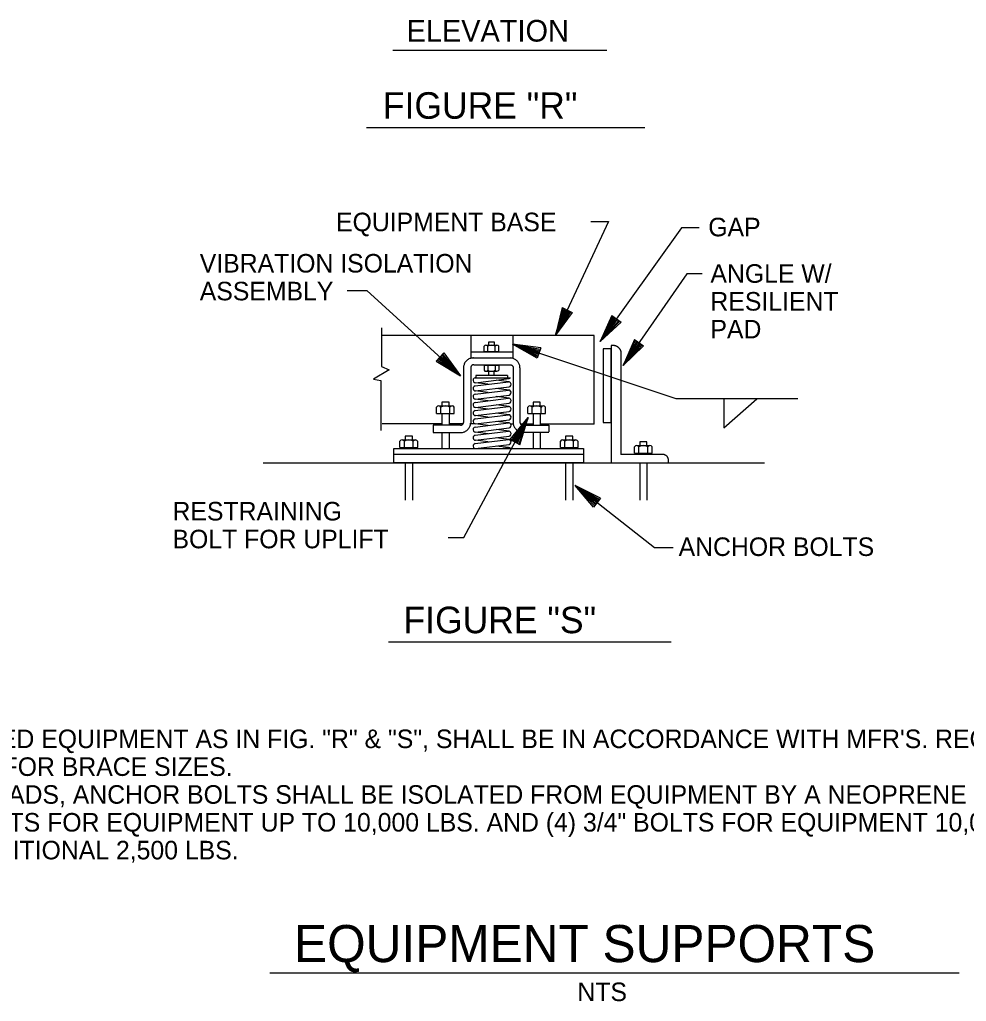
# Model space of a CAD drawing. Extents: x 10040.55 to 10045.84, y 10033.26 to 10035.76.
# Drawn here: x 10042.746 to 10043.256, y 10034.644 to 10035.174 of the extents above; entities that cross this region are included whole.
import ezdxf

# ---------------------------------------------------------------- set-up
doc = ezdxf.new("R2010")
doc.units = 0
doc.layers.add('Level 2', color=7, linetype='Continuous')

msp = doc.modelspace()

# ---------------------------------------------------------------- linework, layer by layer
at = {"layer": 'Level 2'}
for p, q in [((10042.94689, 10035.15714), (10043.06232, 10035.15714)), ((10042.93277, 10035.11534), (10043.08279, 10035.11534)), ((10043.03826, 10035.01825), (10043.03459, 10035.00334)), ((10043.03826, 10035.01825), (10043.04371, 10035.01569)), ((10043.03459, 10035.00334), (10043.03895, 10035.01793)), ((10043.03459, 10035.00334), (10043.03972, 10035.01759)), ((10043.03459, 10035.00334), (10043.04032, 10035.01728)), ((10043.04096, 10035.017), (10043.03459, 10035.00334)), ((10043.03459, 10035.00334), (10043.04164, 10035.01667)), ((10043.03459, 10035.00334), (10043.04232, 10035.01636)), ((10043.03459, 10035.00334), (10043.04297, 10035.01604)), ((10043.04371, 10035.01569), (10043.03459, 10035.00334)), ((10043.06508, 10035.01396), (10043.05876, 10034.99997)), ((10043.05876, 10034.99997), (10043.06571, 10035.01351)), ((10043.05876, 10034.99997), (10043.06641, 10035.01304)), ((10043.06508, 10035.01396), (10043.06998, 10035.01045)), ((10043.05876, 10034.99997), (10043.06694, 10035.01264)), ((10043.06751, 10035.01223), (10043.05876, 10034.99997)), ((10043.05876, 10034.99997), (10043.06811, 10035.01178)), ((10043.05876, 10034.99997), (10043.06873, 10035.01136)), ((10043.05876, 10034.99997), (10043.06931, 10035.01093)), ((10043.06998, 10035.01045), (10043.05876, 10034.99997)), ((10043.05557, 10035.00319), (10042.94107, 10035.00319)), ((10043.05557, 10034.95544), (10043.05557, 10035.00319)), ((10042.99614, 10034.99466), (10042.99614, 10034.99741)), ((10042.99713, 10034.998), (10043.00304, 10034.998)), ((10042.99809, 10034.99466), (10042.99809, 10034.99741)), ((10043.00206, 10034.99466), (10043.00206, 10034.99741)), ((10043.00403, 10034.99466), (10043.00403, 10034.99739)), ((10043.01153, 10034.99855), (10043.09949, 10034.96918)), ((10043.02583, 10034.9938), (10043.01153, 10034.99855)), ((10043.02484, 10034.99092), (10043.01153, 10034.99855)), ((10043.02676, 10034.99664), (10043.01153, 10034.99855)), ((10043.01153, 10034.99855), (10043.02535, 10034.99238)), ((10043.01153, 10034.99855), (10043.02627, 10034.99509)), ((10043.01153, 10034.99855), (10043.02511, 10034.9917)), ((10043.01153, 10034.99855), (10043.02558, 10034.99308)), ((10043.01153, 10034.99855), (10043.02604, 10034.99447)), ((10043.01153, 10034.99855), (10043.02652, 10034.99591)), ((10043.06473, 10034.99783), (10043.06473, 10034.93447)), ((10043.06656, 10034.99783), (10043.06473, 10034.99783)), ((10043.07724, 10035.00113), (10043.07113, 10034.98704)), ((10043.07113, 10034.98704), (10043.07786, 10035.00069)), ((10043.07113, 10034.98704), (10043.07857, 10035.00023)), ((10043.07113, 10034.98704), (10043.0791, 10034.99982)), ((10043.07969, 10034.99944), (10043.07113, 10034.98704)), ((10043.07113, 10034.98704), (10043.0803, 10034.999)), ((10043.07113, 10034.98704), (10043.08093, 10034.99858)), ((10043.07113, 10034.98704), (10043.08151, 10034.99816)), ((10043.08218, 10034.99768), (10043.07113, 10034.98704)), ((10043.07724, 10035.00113), (10043.08218, 10034.99768)), ((10042.97029, 10034.98933), (10042.97436, 10034.99378)), ((10042.98345, 10034.98142), (10042.97281, 10034.99209)), ((10042.98345, 10034.98142), (10042.97331, 10034.99266)), ((10042.98345, 10034.98142), (10042.9738, 10034.99319)), ((10042.97436, 10034.99378), (10042.98345, 10034.98142)), ((10042.98891, 10034.99439), (10043.0118, 10034.99439)), ((10042.99614, 10034.99466), (10043.00403, 10034.99466)), ((10043.02676, 10034.99664), (10043.02484, 10034.99092)), ((10043.06035, 10034.99595), (10043.06035, 10034.95638)), ((10043.06473, 10034.99595), (10043.06035, 10034.99595)), ((10043.06473, 10034.95638), (10043.06473, 10034.99595)), ((10043.0699, 10034.99424), (10043.0699, 10034.93901)), ((10042.97029, 10034.98933), (10042.98345, 10034.98142)), ((10042.98345, 10034.98142), (10042.97081, 10034.98991)), ((10042.98345, 10034.98142), (10042.97136, 10034.99054)), ((10042.98345, 10034.98142), (10042.97183, 10034.99102)), ((10042.97229, 10034.99155), (10042.98345, 10034.98142)), ((10042.99055, 10034.98744), (10043.01017, 10034.98744)), ((10042.99614, 10034.98724), (10043.00403, 10034.98724)), ((10042.99614, 10034.98724), (10042.99614, 10034.98449)), ((10042.99809, 10034.98724), (10042.99809, 10034.98449)), ((10043.00206, 10034.98724), (10043.00206, 10034.98449)), ((10043.00403, 10034.98724), (10043.00403, 10034.98451)), ((10042.98503, 10034.98577), (10042.98503, 10034.95627)), ((10042.98889, 10034.98586), (10042.98889, 10034.95599)), ((10043.00869, 10034.98171), (10042.99166, 10034.98171)), ((10042.99166, 10034.98171), (10042.99166, 10034.98046)), ((10042.99713, 10034.9839), (10043.00304, 10034.9839)), ((10042.99853, 10034.98393), (10042.99853, 10034.98169)), ((10043.00157, 10034.98169), (10043.00157, 10034.98393)), ((10043.00869, 10034.98171), (10043.00869, 10034.98046)), ((10043.01178, 10034.98577), (10043.01178, 10034.95629)), ((10043.01548, 10034.98577), (10043.01548, 10034.95629)), ((10042.99128, 10034.98046), (10043.0104, 10034.98046)), ((10042.9983, 10034.97689), (10042.99128, 10034.97774)), ((10042.99129, 10034.97602), (10043.00932, 10034.97824)), ((10042.99155, 10034.97775), (10043.00957, 10034.97997)), ((10043.00958, 10034.97824), (10043.00255, 10034.9791)), ((10042.99128, 10034.97158), (10043.0093, 10034.9738)), ((10042.99831, 10034.97245), (10042.9913, 10034.9733)), ((10042.99155, 10034.96888), (10043.00957, 10034.97109)), ((10042.99156, 10034.97331), (10043.00959, 10034.97553)), ((10043.0096, 10034.9738), (10043.00256, 10034.97467)), ((10042.97169, 10034.96528), (10042.97885, 10034.96528)), ((10042.9983, 10034.96801), (10042.99128, 10034.96886)), ((10042.99129, 10034.96715), (10043.00932, 10034.96936)), ((10042.99156, 10034.96444), (10043.00959, 10034.96666)), ((10043.00958, 10034.96936), (10043.00255, 10034.97023)), ((10043.0096, 10034.96493), (10043.00256, 10034.96579)), ((10043.02089, 10034.96528), (10043.02805, 10034.96528)), ((10043.09949, 10034.96918), (10043.16543, 10034.96918)), ((10043.12538, 10034.96915), (10043.12538, 10034.9534)), ((10043.12538, 10034.9534), (10043.14317, 10034.96902)), ((10042.97049, 10034.96122), (10042.97049, 10034.96455)), ((10042.97049, 10034.96122), (10042.98004, 10034.96122)), ((10042.97285, 10034.96122), (10042.97285, 10034.96455)), ((10042.97331, 10034.96122), (10042.97331, 10034.95489)), ((10042.97724, 10034.96122), (10042.97724, 10034.95496)), ((10042.97766, 10034.96122), (10042.97766, 10034.96455)), ((10042.98004, 10034.96122), (10042.98004, 10034.96453)), ((10042.99128, 10034.96271), (10043.0093, 10034.96493)), ((10042.9983, 10034.95914), (10042.99128, 10034.95999)), ((10042.99129, 10034.95827), (10043.00932, 10034.96049)), ((10042.99831, 10034.96357), (10042.9913, 10034.96443)), ((10042.99155, 10034.96), (10043.00957, 10034.96222)), ((10043.00958, 10034.96049), (10043.00255, 10034.96135)), ((10043.01969, 10034.96122), (10043.01969, 10034.96455)), ((10043.01969, 10034.96122), (10043.02924, 10034.96122)), ((10043.02205, 10034.96122), (10043.02205, 10034.96455)), ((10043.02251, 10034.96122), (10043.02251, 10034.95489)), ((10043.02644, 10034.96122), (10043.02644, 10034.95484)), ((10043.02685, 10034.96122), (10043.02685, 10034.96455)), ((10043.02924, 10034.96122), (10043.02924, 10034.96453)), ((10042.97331, 10034.95552), (10042.94107, 10034.95555)), ((10042.98342, 10034.95492), (10042.96871, 10034.95492)), ((10042.96871, 10034.95492), (10042.96871, 10034.95088)), ((10042.98479, 10034.9555), (10042.97724, 10034.95551)), ((10042.99138, 10034.9555), (10042.98878, 10034.9555)), ((10042.99128, 10034.95383), (10043.0093, 10034.95605)), ((10042.99831, 10034.9547), (10042.9913, 10034.95555)), ((10042.99156, 10034.95556), (10043.00959, 10034.95778)), ((10043.0096, 10034.95605), (10043.00256, 10034.95692)), ((10043.01018, 10034.94713), (10043.01998, 10034.95894)), ((10043.01185, 10034.95548), (10043.01044, 10034.95548)), ((10043.01998, 10034.95894), (10043.0109, 10034.94673)), ((10043.01998, 10034.95894), (10043.01153, 10034.94638)), ((10043.01998, 10034.95894), (10043.01219, 10034.94603)), ((10043.01285, 10034.94567), (10043.01998, 10034.95894)), ((10043.01998, 10034.95894), (10043.01347, 10034.94534)), ((10043.01998, 10034.95894), (10043.01405, 10034.94501)), ((10043.01998, 10034.95894), (10043.0148, 10034.94463)), ((10043.01548, 10034.94426), (10043.01998, 10034.95894)), ((10043.02251, 10034.95547), (10043.01572, 10034.95548)), ((10043.01694, 10034.95484), (10043.03106, 10034.95484)), ((10043.05557, 10034.95544), (10043.02644, 10034.95547)), ((10043.03106, 10034.95481), (10043.03106, 10034.95121)), ((10043.06035, 10034.95638), (10043.06473, 10034.95638)), ((10042.96871, 10034.95082), (10042.9832, 10034.95082)), ((10042.97331, 10034.95082), (10042.97331, 10034.94225)), ((10042.97724, 10034.95082), (10042.97724, 10034.94225)), ((10042.9983, 10034.95025), (10042.99128, 10034.95111)), ((10042.99129, 10034.9494), (10043.00932, 10034.9516)), ((10042.99155, 10034.95113), (10043.00957, 10034.95333)), ((10043.00958, 10034.9516), (10043.00255, 10034.95247)), ((10043.01704, 10034.95116), (10043.03106, 10034.95116)), ((10043.02251, 10034.95116), (10043.02251, 10034.94225)), ((10043.02644, 10034.95116), (10043.02644, 10034.94225)), ((10042.95074, 10034.94281), (10042.95074, 10034.94615)), ((10042.95194, 10034.94688), (10042.9591, 10034.94688)), ((10042.9531, 10034.94281), (10042.9531, 10034.94615)), ((10042.95791, 10034.94281), (10042.95791, 10034.94615)), ((10042.96029, 10034.94281), (10042.96029, 10034.94613)), ((10042.99128, 10034.94496), (10043.0093, 10034.94717)), ((10042.99831, 10034.94581), (10042.9913, 10034.94668)), ((10042.99155, 10034.94225), (10043.00957, 10034.94446)), ((10042.99156, 10034.94669), (10043.00959, 10034.9489)), ((10043.0096, 10034.94717), (10043.00256, 10034.94803)), ((10043.01548, 10034.94426), (10043.01018, 10034.94713)), ((10043.03726, 10034.94281), (10043.03726, 10034.94615)), ((10043.03846, 10034.94688), (10043.04563, 10034.94688)), ((10043.03963, 10034.94281), (10043.03963, 10034.94615)), ((10043.04443, 10034.94281), (10043.04443, 10034.94615)), ((10043.04681, 10034.94281), (10043.04681, 10034.94613)), ((10042.94741, 10034.9393), (10043.04974, 10034.9393)), ((10042.95074, 10034.94281), (10042.96029, 10034.94281)), ((10043.00931, 10034.94277), (10043.00255, 10034.94359)), ((10043.00506, 10034.94225), (10043.00931, 10034.94277)), ((10043.03726, 10034.94281), (10043.04681, 10034.94281)), ((10043.09283, 10034.93901), (10043.0699, 10034.93901)), ((10043.07725, 10034.9398), (10043.07725, 10034.94314)), ((10043.07725, 10034.9398), (10043.0868, 10034.9398)), ((10043.07845, 10034.94386), (10043.08561, 10034.94386)), ((10043.07961, 10034.9398), (10043.07961, 10034.94314)), ((10043.08442, 10034.9398), (10043.08442, 10034.94314)), ((10043.0868, 10034.9398), (10043.0868, 10034.94311)), ((10042.87695, 10034.93447), (10043.14744, 10034.93447)), ((10042.95356, 10034.93448), (10042.95356, 10034.9145)), ((10042.95749, 10034.93448), (10042.95749, 10034.9145)), ((10043.04008, 10034.93448), (10043.04008, 10034.9145)), ((10043.04401, 10034.93448), (10043.04401, 10034.9145)), ((10043.06473, 10034.93447), (10043.09555, 10034.93447)), ((10043.08007, 10034.93448), (10043.08007, 10034.9145)), ((10043.084, 10034.93448), (10043.084, 10034.9145)), ((10043.09555, 10034.93447), (10043.09555, 10034.93615)), ((10043.0571, 10034.91308), (10043.04527, 10034.92241)), ((10043.05521, 10034.91071), (10043.04527, 10034.92241)), ((10043.05895, 10034.91544), (10043.04527, 10034.92241)), ((10043.04527, 10034.92241), (10043.05618, 10034.91191)), ((10043.04527, 10034.92241), (10043.05797, 10034.91416)), ((10043.04527, 10034.92241), (10043.05572, 10034.91134)), ((10043.04527, 10034.92241), (10043.05664, 10034.9125)), ((10043.04527, 10034.92241), (10043.05753, 10034.91365)), ((10043.04527, 10034.92241), (10043.05847, 10034.91483)), ((10043.05895, 10034.91544), (10043.05521, 10034.91071)), ((10042.94463, 10034.83795), (10043.09708, 10034.83795)), ((10042.88048, 10034.65958), (10043.25249, 10034.65958))]:
    msp.add_line(p, q, dxfattribs=at)
for points in [[(10043.05371, 10035.0646), (10043.06326, 10035.0646), (10043.03459, 10035.00334)], [(10043.11216, 10035.06124), (10043.1026, 10035.06124), (10043.05876, 10034.99997)], [(10043.11384, 10035.0365), (10043.10542, 10035.0365), (10043.07113, 10034.98704)], [(10042.92218, 10035.02751), (10042.93285, 10035.02751), (10042.98345, 10034.98142)], [(10042.94072, 10035.00726), (10042.94072, 10034.98647), (10042.94493, 10034.98478), (10042.9365, 10034.97972), (10042.94044, 10034.97888), (10042.94044, 10034.9519)], [(10043.00171, 10034.99802), (10043.00171, 10034.99968), (10042.99847, 10034.99968), (10042.99847, 10034.99802)], [(10043.06656, 10034.99783), (10043.06675, 10034.99778), (10043.06695, 10034.99773), (10043.06714, 10034.99767), (10043.06732, 10034.99759), (10043.0675, 10034.99751), (10043.06768, 10034.99742), (10043.06785, 10034.99732), (10043.06802, 10034.99722), (10043.06819, 10034.9971), (10043.06834, 10034.99698), (10043.0685, 10034.99685), (10043.06865, 10034.99671), (10043.06878, 10034.99657), (10043.06892, 10034.99643), (10043.06904, 10034.99627), (10043.06916, 10034.9961), (10043.06927, 10034.99594), (10043.06938, 10034.99577), (10043.06947, 10034.99559), (10043.06955, 10034.99542), (10043.06964, 10034.99523), (10043.0697, 10034.99504), (10043.06976, 10034.99485), (10043.06981, 10034.99467), (10043.06991, 10034.99424)], [(10042.99049, 10034.99114), (10042.99007, 10034.99113), (10042.98965, 10034.99107), (10042.98924, 10034.99099), (10042.98883, 10034.99088), (10042.98834, 10034.99073), (10042.98796, 10034.99055), (10042.98759, 10034.99034), (10042.98724, 10034.99011), (10042.98691, 10034.98985), (10042.9866, 10034.98956), (10042.98631, 10034.98926), (10042.98605, 10034.98893), (10042.98582, 10034.98857), (10042.98561, 10034.98821), (10042.98544, 10034.98782), (10042.98529, 10034.98743), (10042.98518, 10034.98702), (10042.98509, 10034.98661), (10042.98504, 10034.9862), (10042.98503, 10034.98577)], [(10042.99055, 10034.98744), (10042.99042, 10034.98743), (10042.99029, 10034.98742), (10042.99016, 10034.9874), (10042.99003, 10034.98735), (10042.98991, 10034.98731), (10042.98979, 10034.98725), (10042.98968, 10034.98719), (10042.98957, 10034.98711), (10042.98947, 10034.98704), (10042.98936, 10034.98695), (10042.98928, 10034.98685), (10042.9892, 10034.98675), (10042.98913, 10034.98664), (10042.98906, 10034.98652), (10042.98901, 10034.98641), (10042.98896, 10034.98628), (10042.98893, 10034.98616), (10042.98891, 10034.98603), (10042.98889, 10034.9859), (10042.98889, 10034.98586)], [(10043.01548, 10034.98577), (10043.01546, 10034.98619), (10043.01541, 10034.9866), (10043.01533, 10034.98701), (10043.01522, 10034.98742), (10043.01507, 10034.98781), (10043.0149, 10034.98819), (10043.0147, 10034.98855), (10043.01446, 10034.9889), (10043.0142, 10034.98923), (10043.01392, 10034.98953), (10043.01361, 10034.98981), (10043.01328, 10034.99007), (10043.01294, 10034.9903), (10043.01257, 10034.99051), (10043.0122, 10034.99069), (10043.0118, 10034.99083), (10043.0114, 10034.99094), (10043.01099, 10034.99102), (10043.01057, 10034.99107), (10043.01016, 10034.99109)], [(10043.01017, 10034.98744), (10043.01029, 10034.98744), (10043.01042, 10034.98742), (10043.01054, 10034.9874), (10043.01067, 10034.98736), (10043.01079, 10034.98732), (10043.01091, 10034.98727), (10043.01102, 10034.98721), (10043.01113, 10034.98714), (10043.01123, 10034.98706), (10043.01132, 10034.98697), (10043.01141, 10034.98688), (10043.01149, 10034.98678), (10043.01156, 10034.98668), (10043.01163, 10034.98656), (10043.01168, 10034.98645), (10043.01173, 10034.98632), (10043.01176, 10034.9862), (10043.01178, 10034.98607), (10043.0118, 10034.98595), (10043.0118, 10034.98582)], [(10042.97724, 10034.9653), (10042.97724, 10034.9673), (10042.97331, 10034.9673), (10042.97331, 10034.9653)], [(10043.02644, 10034.9653), (10043.02644, 10034.9673), (10043.02251, 10034.9673), (10043.02251, 10034.9653)], [(10042.9767, 10034.8943), (10042.98514, 10034.8943), (10043.01998, 10034.95894)], [(10042.9832, 10034.95082), (10042.98365, 10034.95083), (10042.98408, 10034.95086), (10042.98451, 10034.95094), (10042.98494, 10034.95104), (10042.98535, 10034.95119), (10042.98576, 10034.95135), (10042.98616, 10034.95156), (10042.98652, 10034.95179), (10042.98688, 10034.95206), (10042.98721, 10034.95235), (10042.98751, 10034.95267), (10042.98779, 10034.95301), (10042.988, 10034.95338), (10042.98822, 10034.95375), (10042.98842, 10034.95415), (10042.98857, 10034.95456), (10042.9887, 10034.95498), (10042.98878, 10034.95542), (10042.98884, 10034.95584), (10042.98884, 10034.95594)], [(10042.98342, 10034.95492), (10042.98354, 10034.95491), (10042.98366, 10034.95491), (10042.98378, 10034.95491), (10042.9839, 10034.95493), (10042.98401, 10034.95496), (10042.98413, 10034.955), (10042.98423, 10034.95504), (10042.98434, 10034.9551), (10042.98444, 10034.95517), (10042.98453, 10034.95524), (10042.98463, 10034.95532), (10042.9847, 10034.95541), (10042.98477, 10034.9555), (10042.98484, 10034.9556), (10042.9849, 10034.95571), (10042.98494, 10034.95582), (10042.98498, 10034.95594), (10042.98501, 10034.95605), (10042.98502, 10034.95617), (10042.98502, 10034.95621)], [(10043.01178, 10034.95629), (10043.0118, 10034.95588), (10043.01185, 10034.95548), (10043.01194, 10034.95507), (10043.01205, 10034.95468), (10043.0122, 10034.9543), (10043.01236, 10034.95393), (10043.01257, 10034.95357), (10043.0128, 10034.95324), (10043.01306, 10034.95292), (10043.01334, 10034.95263), (10043.01365, 10034.95234), (10043.01397, 10034.9521), (10043.01431, 10034.95188), (10043.01467, 10034.95169), (10043.01504, 10034.95152), (10043.01543, 10034.95139), (10043.01582, 10034.95128), (10043.01623, 10034.95121), (10043.01664, 10034.95117), (10043.01704, 10034.95116)], [(10043.01548, 10034.95629), (10043.01548, 10034.95617), (10043.0155, 10034.95605), (10043.01553, 10034.95594), (10043.01556, 10034.95582), (10043.0156, 10034.95571), (10043.01566, 10034.9556), (10043.01572, 10034.9555), (10043.01579, 10034.95541), (10043.01588, 10034.95531), (10043.01596, 10034.95523), (10043.01605, 10034.95516), (10043.01615, 10034.95508), (10043.01625, 10034.95502), (10043.01635, 10034.95497), (10043.01647, 10034.95493), (10043.01658, 10034.9549), (10043.0167, 10034.95486), (10043.01681, 10034.95485), (10043.01694, 10034.95484), (10043.01705, 10034.95484)], [(10042.95749, 10034.9469), (10042.95749, 10034.9489), (10042.95356, 10034.9489), (10042.95356, 10034.9469)], [(10043.04401, 10034.9469), (10043.04401, 10034.9489), (10043.04008, 10034.9489), (10043.04008, 10034.9469)], [(10043.084, 10034.94389), (10043.084, 10034.94589), (10043.08007, 10034.94589), (10043.08007, 10034.94389)], [(10043.09553, 10034.93594), (10043.09554, 10034.93613), (10043.09554, 10034.93632), (10043.09552, 10034.93651), (10043.09549, 10034.93671), (10043.09545, 10034.9369), (10043.09539, 10034.93708), (10043.09532, 10034.93726), (10043.09524, 10034.93744), (10043.09515, 10034.93761), (10043.09504, 10034.93777), (10043.09493, 10034.93793), (10043.0948, 10034.93808), (10043.09467, 10034.93822), (10043.09452, 10034.93834), (10043.09436, 10034.93847), (10043.09421, 10034.93857), (10043.09403, 10034.93868), (10043.09386, 10034.93876), (10043.09368, 10034.93883), (10043.0935, 10034.9389), (10043.09331, 10034.93895), (10043.09311, 10034.93898), (10043.09293, 10034.93901), (10043.09283, 10034.93901)], [(10043.0981, 10034.88868), (10043.08799, 10034.88868), (10043.04527, 10034.92241)]]:
    msp.add_lwpolyline(points, dxfattribs=at)
for points in [[(10042.9889, 10035.00319), (10042.9889, 10034.99114), (10043.0118, 10034.99114), (10043.0118, 10035.00319)], [(10042.94741, 10034.93448), (10042.94741, 10034.94225), (10043.04974, 10034.94225), (10043.04974, 10034.93448)]]:
    msp.add_lwpolyline(points, close=True, dxfattribs=at)
for centre, radius, start, end in [((10042.99712, 10034.9969), 0.0011, 27.8877, 152.0342), ((10043.00008, 10034.99435), 0.00365, 57.0062, 122.943), ((10043.00304, 10034.99689), 0.0011, 26.7827, 151.8391), ((10042.99712, 10034.985), 0.0011, 207.9658, 332.1123), ((10043.00008, 10034.98754), 0.00365, 237.057, 302.9938), ((10043.00304, 10034.98501), 0.0011, 208.1609, 333.2173), ((10042.97168, 10034.96394), 0.00134, 27.8877, 152.0342), ((10042.97526, 10034.96086), 0.00441, 57.0062, 122.943), ((10042.97884, 10034.96393), 0.00134, 26.7827, 151.8391), ((10043.02088, 10034.96394), 0.00134, 27.8877, 152.0342), ((10043.02446, 10034.96086), 0.00441, 57.0062, 122.943), ((10043.02804, 10034.96393), 0.00134, 26.7827, 151.8391), ((10042.95193, 10034.94553), 0.00134, 27.8877, 152.0342), ((10042.95551, 10034.94245), 0.00441, 57.0062, 122.943), ((10042.95909, 10034.94552), 0.00134, 26.7827, 151.8391), ((10043.03845, 10034.94553), 0.00134, 27.8877, 152.0342), ((10043.04203, 10034.94245), 0.00441, 57.0062, 122.943), ((10043.04561, 10034.94552), 0.00134, 26.7827, 151.8391), ((10043.07844, 10034.94252), 0.00134, 27.8877, 152.0342), ((10043.08202, 10034.93944), 0.00441, 57.0062, 122.943), ((10043.0856, 10034.94251), 0.00134, 26.7827, 151.8391)]:
    msp.add_arc(centre, radius, start, end, dxfattribs=at)
for centre, major_axis, start_param, end_param in [((10042.99141, 10034.9791), (0, -0.00136), 3.251722, 6.393315), ((10042.99143, 10034.97466), (0, -0.00136), 3.251722, 6.393315), ((10043.00945, 10034.97688), (0, 0.00136), 3.251722, 6.393315), ((10043.00944, 10034.98132), (0, 0.00136), 3.251722, 4.030489), ((10042.99141, 10034.97022), (0, -0.00136), 3.251722, 6.393315), ((10043.00944, 10034.97244), (0, 0.00136), 3.251722, 6.393315), ((10042.99143, 10034.96579), (0, -0.00136), 3.251722, 6.393315), ((10043.00945, 10034.968), (0, 0.00136), 3.251722, 6.393315), ((10042.99141, 10034.96135), (0, -0.00136), 3.251722, 6.393315), ((10043.00944, 10034.96357), (0, 0.00136), 3.251722, 6.393315), ((10043.00945, 10034.95913), (0, 0.00136), 3.251722, 6.393315), ((10042.99143, 10034.95691), (0, -0.00136), 3.251722, 6.393315), ((10043.00944, 10034.95469), (0, 0.00136), 3.251722, 6.393315), ((10042.99141, 10034.95247), (0, -0.00136), 3.251722, 6.393315), ((10043.00945, 10034.95025), (0, 0.00136), 3.251722, 6.393315), ((10042.99141, 10034.9436), (0, -0.00136), 3.251722, 6.393315), ((10042.99143, 10034.94804), (0, -0.00136), 3.251722, 6.393315), ((10043.00944, 10034.94582), (0, 0.00136), 3.251722, 6.393315), ((10043.00931, 10034.94141), (0, 0.00136), 5.361733, 6.39416)]:
    msp.add_ellipse(centre, major_axis=major_axis, ratio=0.9, start_param=start_param, end_param=end_param, dxfattribs=at)

# ---------------------------------------------------------------- texts
for s, height, p in [('ELEVATION', 0.011667, (10042.9543, 10035.16168)), ('FIGURE "R"', 0.014301, (10042.94154, 10035.12008)), ('EQUIPMENT BASE', 0.01, (10042.91625, 10035.05942)), ('GAP ', 0.01, (10043.11706, 10035.05668)), ('VIBRATION ISOLATION', 0.01, (10042.84273, 10035.03716)), ('ANGLE W/', 0.01, (10043.11822, 10035.03163)), ('ASSEMBLY', 0.01, (10042.84273, 10035.02216)), ('RESILIENT ', 0.01, (10043.11822, 10035.01663)), ('PAD', 0.01, (10043.11822, 10035.00163)), ('RESTRAINING', 0.01, (10042.82802, 10034.90347)), ('BOLT FOR UPLIFT', 0.01, (10042.82802, 10034.88847)), ('ANCHOR BOLTS', 0.01, (10043.10106, 10034.88433)), ('FIGURE "S"', 0.014301, (10042.95268, 10034.84268)), ('1. CLEARANCES AT SIDES FOR SPRING MOUNTED EQUIPMENT AS IN FIG. "R" & "S", SHALL BE IN ACCORDANCE WITH MFR\'S. RECOMMENDATIONS.', 0.01, (10042.42507, 10034.78073)), ('2. SEE MAXIMUM BRACING LENGTHS, TABLE 1, FOR BRACE SIZES.', 0.01, (10042.4265, 10034.76573)), ('3. IF EQUIPMENT IS MOUNTED ON NEOPRENE PADS, ANCHOR BOLTS SHALL BE ISOLATED FROM EQUIPMENT BY A NEOPRENE SLEEVE AND WASHER.', 0.01, (10042.4265, 10034.75073)), ('4. PROVIDE A MINIMUM OF (4) 1/2" ANCHOR BOLTS FOR EQUIPMENT UP TO 10,000 LBS. AND (4) 3/4" BOLTS FOR EQUIPMENT 10,000 LBS. OR GREATER.', 0.01, (10042.4265, 10034.73573)), ('   ADD (1) ADDITIONAL 3/4" BOLT FOR EACH ADDITIONAL 2,500 LBS.', 0.01, (10042.42794, 10034.72073)), ('EQUIPMENT SUPPORTS', 0.02, (10042.89359, 10034.66533)), ('NTS', 0.01, (10043.04646, 10034.64431))]:
    msp.add_text(s, height=height, dxfattribs=at).set_placement(p)

doc.saveas('drawing.dxf')
